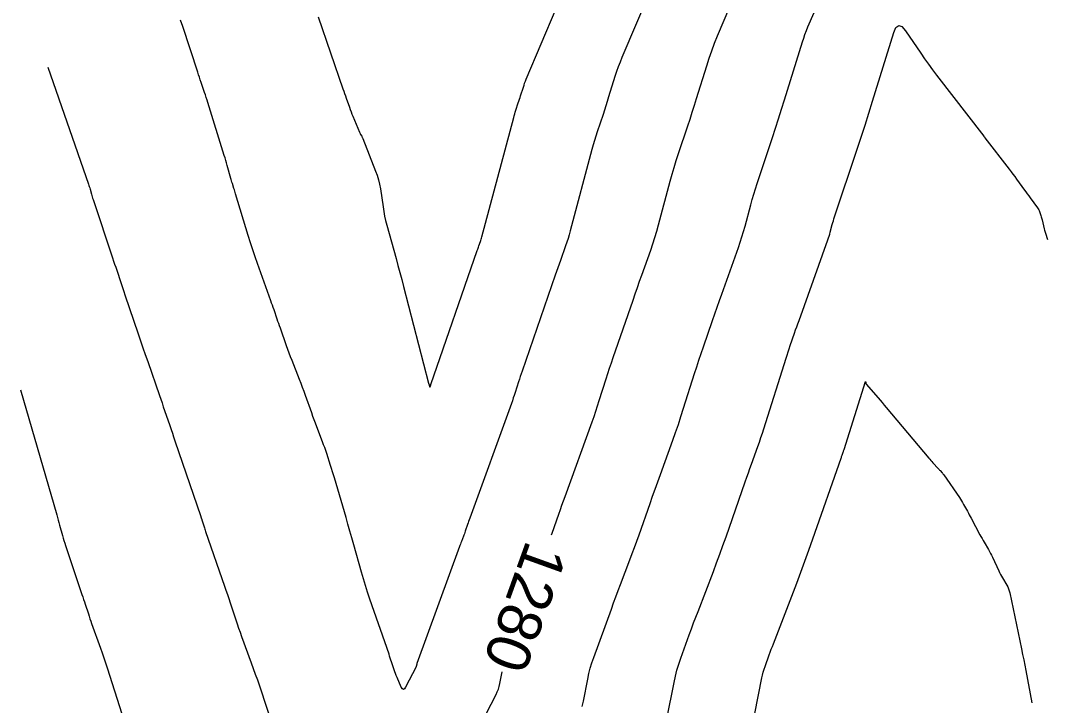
# Model space of a CAD drawing. Extents: x 658976 to 668726, y 639543 to 647196.
# Drawn here: x 661414.9 to 661555.9, y 640275.8 to 640369.9 of the extents above; entities that cross this region are included whole.
import ezdxf

# ---------------------------------------------------------------- set-up
doc = ezdxf.new("R2010")
doc.units = 0
for name, color, linetype in [('Ex_Contour Labels', 7, 'Continuous'), ('Ex_Major Contours', 7, 'Continuous'), ('Ex_Minor Contours', 7, 'Continuous')]:
    doc.layers.add(name, color=color, linetype=linetype)

msp = doc.modelspace()

# ---------------------------------------------------------------- linework, layer by layer
at = {"layer": 'Ex_Major Contours'}
for points in [[(661487.8, 640299.25), (661487.89, 640299.5), (661488.8, 640302.11), (661489.01, 640302.71), (661489.22, 640303.32), (661489.44, 640303.92), (661489.66, 640304.53), (661493.37, 640314.77), (661493.63, 640315.5), (661493.88, 640316.23), (661494.12, 640316.96), (661494.36, 640317.7), (661495.29, 640320.65), (661495.52, 640321.38), (661495.76, 640322.12), (661496.01, 640322.85), (661496.26, 640323.58), (661498.99, 640331.49), (661499.29, 640332.35), (661499.59, 640333.2), (661499.89, 640334.06), (661500.2, 640334.91), (661501.42, 640338.33), (661501.72, 640339.19), (661502, 640340.05), (661502.26, 640340.92), (661502.5, 640341.8), (661504.1, 640347.79), (661504.36, 640348.75), (661504.64, 640349.7), (661504.93, 640350.65), (661505.24, 640351.6), (661506.5, 640355.38), (661506.81, 640356.32), (661507.12, 640357.27), (661507.42, 640358.22), (661507.72, 640359.17), (661509.1, 640363.66), (661509.44, 640364.7), (661509.8, 640365.72), (661510.18, 640366.74), (661510.59, 640367.74), (661512.28, 640371.75)], [(661418.65, 640363.47), (661424.23, 640347.41), (661424.29, 640347.23), (661424.34, 640347.06), (661424.4, 640346.89), (661424.45, 640346.71), (661424.64, 640346.01), (661424.69, 640345.83), (661424.75, 640345.66), (661424.8, 640345.49), (661424.86, 640345.31), (661427.55, 640337.26), (661427.69, 640336.84), (661427.83, 640336.42), (661427.97, 640336), (661428.11, 640335.58), (661428.66, 640333.9), (661428.8, 640333.48), (661428.94, 640333.06), (661429.08, 640332.64), (661429.23, 640332.22), (661431.07, 640326.84), (661431.39, 640325.89), (661431.72, 640324.94), (661432.04, 640323.99), (661432.37, 640323.05), (661433.98, 640318.4), (661434.15, 640317.88), (661434.33, 640317.36), (661434.51, 640316.84), (661434.69, 640316.32), (661435.39, 640314.25), (661435.57, 640313.73), (661435.75, 640313.21), (661435.92, 640312.69), (661436.1, 640312.17), (661439.64, 640301.78), (661439.66, 640301.73), (661439.68, 640301.68), (661439.69, 640301.63), (661439.71, 640301.58), (661439.78, 640301.38), (661439.79, 640301.33), (661439.81, 640301.28), (661439.83, 640301.23), (661439.84, 640301.18), (661440.11, 640300.35), (661440.17, 640300.2), (661440.22, 640300.04), (661440.27, 640299.89), (661440.32, 640299.73), (661442.91, 640292.22), (661443.11, 640291.64), (661443.3, 640291.06), (661443.5, 640290.49), (661443.69, 640289.91), (661444.45, 640287.59), (661444.65, 640287.02), (661444.84, 640286.44), (661445.05, 640285.87), (661445.26, 640285.29), (661446.58, 640281.7), (661446.86, 640280.92), (661447.14, 640280.12), (661447.42, 640279.33), (661447.69, 640278.53), (661449.73, 640272.37)], [(661472.5, 640262.47), (661480.18, 640277.33), (661480.35, 640277.69), (661480.5, 640278.07), (661480.62, 640278.45), (661480.71, 640278.84), (661481.02, 640280.43), (661481.03, 640280.43)]]:
    msp.add_lwpolyline(points, dxfattribs=at)
at = {"layer": 'Ex_Minor Contours'}
for points in [[(661455.75, 640370.37), (661459.17, 640360.46), (661459.28, 640360.15), (661459.39, 640359.83), (661459.5, 640359.52), (661459.61, 640359.21), (661460.05, 640357.95), (661460.17, 640357.64), (661460.28, 640357.32), (661460.4, 640357.01), (661460.53, 640356.71), (661461.44, 640354.51), (661461.47, 640354.44), (661461.51, 640354.37), (661461.54, 640354.3), (661461.58, 640354.23), (661461.75, 640353.96), (661461.79, 640353.89), (661461.82, 640353.82), (661461.86, 640353.75), (661461.89, 640353.68), (661463.65, 640349.2), (661463.86, 640348.61), (661464.04, 640348), (661464.18, 640347.39), (661464.3, 640346.77), (661464.67, 640344.26), (661464.77, 640343.63), (661464.89, 640343.01), (661465.03, 640342.39), (661465.19, 640341.78), (661466.45, 640337.2), (661466.71, 640336.23), (661466.97, 640335.27), (661467.23, 640334.3), (661467.48, 640333.33), (661470.93, 640320.07), (661470.98, 640319.86), (661470.99, 640319.83), (661471, 640319.81), (661471, 640319.78), (661471.01, 640319.76), (661471.07, 640319.57), (661471.08, 640319.54), (661471.1, 640319.53), (661471.11, 640319.54), (661471.13, 640319.57), (661471.22, 640319.84), (661471.23, 640319.85), (661471.23, 640319.87), (661471.24, 640319.88), (661477.6, 640338.29), (661477.66, 640338.45), (661477.71, 640338.6), (661477.76, 640338.75), (661477.82, 640338.91), (661478.04, 640339.52), (661478.09, 640339.67), (661478.14, 640339.83), (661478.19, 640339.98), (661478.23, 640340.14), (661482.61, 640356.54), (661482.68, 640356.79), (661482.75, 640357.04), (661482.83, 640357.29), (661482.91, 640357.54), (661483.24, 640358.54), (661483.33, 640358.79), (661483.41, 640359.04), (661483.49, 640359.29), (661483.56, 640359.54), (661483.93, 640360.72), (661484.02, 640361), (661484.11, 640361.27), (661484.22, 640361.55), (661484.33, 640361.82), (661490.5, 640376.42)], [(661501.33, 640373.94), (661497.47, 640364.8), (661497.2, 640364.15), (661496.96, 640363.5), (661496.72, 640362.84), (661496.51, 640362.17), (661495.64, 640359.36), (661495.45, 640358.76), (661495.26, 640358.16), (661495.07, 640357.56), (661494.87, 640356.96), (661494.08, 640354.57), (661493.88, 640353.97), (661493.7, 640353.37), (661493.52, 640352.77), (661493.35, 640352.16), (661490.37, 640340.97), (661490.22, 640340.45), (661490.07, 640339.94), (661489.9, 640339.43), (661489.73, 640338.93), (661489.01, 640336.91), (661488.83, 640336.41), (661488.65, 640335.9), (661488.47, 640335.4), (661488.3, 640334.89), (661483.75, 640321.73), (661483.62, 640321.36), (661483.5, 640320.99), (661483.38, 640320.63), (661483.26, 640320.26), (661482.79, 640318.77), (661482.67, 640318.4), (661482.55, 640318.04), (661482.43, 640317.67), (661482.3, 640317.3), (661476.57, 640301.52), (661476.5, 640301.31), (661476.42, 640301.1), (661476.35, 640300.89), (661476.27, 640300.67), (661475.96, 640299.77), (661475.9, 640299.59), (661475.83, 640299.41), (661475.76, 640299.23), (661475.7, 640299.05), (661475.42, 640298.34), (661475.36, 640298.16), (661475.29, 640297.99), (661475.22, 640297.81), (661475.16, 640297.63), (661469.32, 640281.57), (661469.31, 640281.53), (661469.3, 640281.49), (661469.29, 640281.45), (661469.28, 640281.41), (661469.25, 640281.26), (661469.24, 640281.22), (661469.23, 640281.18), (661469.22, 640281.14), (661469.2, 640281.11), (661467.76, 640278.32), (661467.61, 640278.1), (661467.46, 640278.03), (661467.32, 640278.11), (661467.18, 640278.34), (661466.6, 640279.68), (661466.49, 640279.94), (661466.39, 640280.2), (661466.29, 640280.46), (661466.2, 640280.73), (661465.85, 640281.8), (661465.76, 640282.06), (661465.67, 640282.33), (661465.58, 640282.6), (661465.49, 640282.86), (661462.86, 640290.44), (661462.55, 640291.36), (661462.25, 640292.28), (661461.97, 640293.21), (661461.7, 640294.15), (661460.66, 640297.9), (661460.4, 640298.84), (661460.13, 640299.77), (661459.86, 640300.71), (661459.59, 640301.64), (661457.99, 640307.09), (661457.86, 640307.51), (661457.74, 640307.92), (661457.61, 640308.34), (661457.47, 640308.75), (661456.94, 640310.4), (661456.8, 640310.81), (661456.66, 640311.22), (661456.51, 640311.63), (661456.36, 640312.04), (661455.58, 640314.08), (661455.4, 640314.56), (661455.22, 640315.03), (661455.05, 640315.51), (661454.88, 640315.99), (661454.03, 640318.38), (661453.83, 640318.93), (661453.63, 640319.49), (661453.42, 640320.04), (661453.2, 640320.6), (661452.18, 640323.2), (661451.99, 640323.7), (661451.8, 640324.2), (661451.62, 640324.71), (661451.43, 640325.21), (661450.58, 640327.62), (661450.47, 640327.93), (661450.36, 640328.25), (661450.25, 640328.56), (661450.14, 640328.87), (661449.71, 640330.13), (661449.6, 640330.44), (661449.5, 640330.76), (661449.38, 640331.07), (661449.27, 640331.38), (661447.44, 640336.48), (661447.11, 640337.44), (661446.78, 640338.4), (661446.47, 640339.36), (661446.17, 640340.33), (661444.42, 640346.07), (661444.37, 640346.25), (661444.31, 640346.43), (661444.26, 640346.6), (661444.2, 640346.78), (661443.99, 640347.49), (661443.93, 640347.66), (661443.88, 640347.84), (661443.83, 640348.02), (661443.78, 640348.19), (661443.29, 640349.95), (661443.2, 640350.3), (661443.09, 640350.65), (661442.99, 640351), (661442.88, 640351.35), (661440.64, 640358.59), (661440.53, 640358.94), (661440.41, 640359.29), (661440.3, 640359.64), (661440.18, 640359.98), (661439.7, 640361.37), (661439.58, 640361.71), (661439.46, 640362.06), (661439.35, 640362.41), (661439.23, 640362.76), (661437.18, 640369.05), (661436.89, 640369.93)], [(661491.99, 640275.68), (661492.17, 640276.42), (661492.77, 640279.45), (661492.93, 640280.2), (661493.12, 640280.94), (661493.34, 640281.68), (661493.59, 640282.4), (661496.01, 640289.06), (661496.32, 640289.91), (661496.63, 640290.76), (661496.95, 640291.61), (661497.28, 640292.45), (661498.57, 640295.83), (661498.89, 640296.68), (661499.21, 640297.53), (661499.52, 640298.38), (661499.82, 640299.24), (661501.32, 640303.54), (661501.67, 640304.54), (661502.02, 640305.54), (661502.38, 640306.54), (661502.74, 640307.54), (661504.44, 640312.23), (661504.83, 640313.32), (661505.21, 640314.42), (661505.57, 640315.52), (661505.93, 640316.62), (661507.44, 640321.41), (661507.73, 640322.33), (661508.03, 640323.24), (661508.33, 640324.15), (661508.64, 640325.06), (661509.9, 640328.69), (661510.21, 640329.6), (661510.53, 640330.5), (661510.85, 640331.41), (661511.17, 640332.31), (661513.46, 640338.72), (661513.71, 640339.44), (661513.94, 640340.16), (661514.16, 640340.89), (661514.37, 640341.63), (661515.15, 640344.57), (661515.35, 640345.31), (661515.57, 640346.04), (661515.79, 640346.76), (661516.03, 640347.49), (661518.13, 640353.8), (661518.55, 640355.09), (661518.97, 640356.38), (661519.38, 640357.68), (661519.79, 640358.98), (661522.25, 640366.93), (661522.41, 640367.45), (661522.59, 640367.96), (661522.78, 640368.47), (661522.99, 640368.97), (661523.83, 640370.97)], [(661503.63, 640274.01), (661504.62, 640279), (661504.8, 640279.84), (661505.01, 640280.67), (661505.26, 640281.49), (661505.54, 640282.3), (661506.71, 640285.53), (661507.01, 640286.34), (661507.3, 640287.15), (661507.61, 640287.95), (661507.91, 640288.75), (661510.01, 640294.22), (661510.46, 640295.41), (661510.9, 640296.59), (661511.33, 640297.78), (661511.75, 640298.97), (661514.39, 640306.55), (661514.6, 640307.16), (661514.82, 640307.77), (661515.03, 640308.37), (661515.25, 640308.97), (661516.13, 640311.39), (661516.34, 640311.99), (661516.55, 640312.6), (661516.75, 640313.21), (661516.95, 640313.82), (661520, 640323.5), (661520.14, 640323.94), (661520.28, 640324.37), (661520.42, 640324.8), (661520.57, 640325.23), (661521.17, 640326.95), (661521.31, 640327.38), (661521.46, 640327.81), (661521.62, 640328.24), (661521.77, 640328.66), (661525.73, 640339.75), (661525.82, 640340.01), (661525.9, 640340.27), (661525.98, 640340.53), (661526.06, 640340.79), (661526.34, 640341.85), (661526.41, 640342.11), (661526.49, 640342.37), (661526.57, 640342.63), (661526.65, 640342.9), (661529.75, 640352.21), (661530.29, 640353.85), (661530.83, 640355.5), (661531.35, 640357.14), (661531.87, 640358.79), (661534.78, 640368.22), (661535.08, 640368.9), (661535.45, 640369.17), (661535.88, 640369.02), (661536.38, 640368.46), (661538.47, 640365.38), (661539, 640364.61), (661539.55, 640363.86), (661540.1, 640363.11), (661540.66, 640362.36), (661547.12, 640353.98), (661547.13, 640353.97), (661547.14, 640353.95), (661547.15, 640353.94), (661547.16, 640353.93), (661547.2, 640353.89), (661547.21, 640353.88), (661547.22, 640353.87), (661547.22, 640353.86), (661547.23, 640353.85), (661547.26, 640353.81), (661547.26, 640353.8), (661547.27, 640353.79), (661547.28, 640353.78), (661547.28, 640353.77), (661550.63, 640349.44), (661550.88, 640349.1), (661551.13, 640348.77), (661551.38, 640348.43), (661551.63, 640348.09), (661552.71, 640346.59), (661552.9, 640346.32), (661553.1, 640346.05), (661553.3, 640345.78), (661553.5, 640345.51), (661554.52, 640344.14), (661554.6, 640344.02), (661554.67, 640343.89), (661554.73, 640343.76), (661554.79, 640343.62), (661554.97, 640343.07), (661555.02, 640342.93), (661555.06, 640342.79), (661555.1, 640342.65), (661555.13, 640342.5), (661555.44, 640341.24), (661555.48, 640341.09), (661555.52, 640340.95), (661555.56, 640340.81), (661555.6, 640340.66), (661555.87, 640339.81)], [(661514.74, 640269.83), (661516.67, 640279.61), (661516.76, 640280.01), (661516.87, 640280.41), (661516.98, 640280.81), (661517.12, 640281.2), (661517.68, 640282.76), (661517.83, 640283.15), (661517.97, 640283.54), (661518.12, 640283.92), (661518.26, 640284.31), (661521.45, 640292.62), (661522.02, 640294.13), (661522.59, 640295.65), (661523.14, 640297.17), (661523.68, 640298.7), (661527.54, 640309.79), (661527.58, 640309.89), (661527.61, 640309.99), (661527.65, 640310.09), (661527.68, 640310.19), (661527.83, 640310.59), (661527.86, 640310.69), (661527.9, 640310.79), (661527.93, 640310.89), (661527.96, 640310.99), (661530.89, 640320.28), (661530.89, 640320.29), (661530.9, 640320.29), (661530.9, 640320.29), (661530.91, 640320.28), (661530.92, 640320.22), (661530.93, 640320.2), (661530.93, 640320.19), (661530.93, 640320.17), (661530.94, 640320.16), (661530.96, 640320.02), (661530.97, 640319.99), (661530.98, 640319.97), (661530.99, 640319.94), (661531.01, 640319.92), (661532.64, 640318.04), (661532.92, 640317.72), (661533.2, 640317.4), (661533.48, 640317.07), (661533.75, 640316.75), (661539.61, 640309.78), (661539.74, 640309.62), (661539.88, 640309.47), (661540.02, 640309.31), (661540.16, 640309.15), (661540.87, 640308.37), (661540.94, 640308.3), (661541.01, 640308.22), (661541.07, 640308.15), (661541.14, 640308.07), (661541.4, 640307.78), (661541.47, 640307.71), (661541.53, 640307.63), (661541.59, 640307.55), (661541.65, 640307.47), (661543.79, 640304.37), (661543.94, 640304.14), (661544.09, 640303.91), (661544.23, 640303.68), (661544.36, 640303.44), (661544.89, 640302.49), (661545.02, 640302.25), (661545.15, 640302.01), (661545.28, 640301.77), (661545.41, 640301.53), (661546.61, 640299.27), (661546.75, 640299.01), (661546.89, 640298.75), (661547.04, 640298.49), (661547.19, 640298.24), (661547.78, 640297.22), (661547.93, 640296.96), (661548.07, 640296.7), (661548.21, 640296.44), (661548.33, 640296.17), (661549.19, 640294.32), (661549.31, 640294.07), (661549.44, 640293.82), (661549.57, 640293.57), (661549.71, 640293.33), (661550.28, 640292.35), (661550.42, 640292.1), (661550.53, 640291.85), (661550.62, 640291.58), (661550.69, 640291.31), (661552.31, 640283.58), (661552.46, 640282.84), (661552.61, 640282.1), (661552.75, 640281.36), (661552.89, 640280.62), (661553.73, 640276.18)], [(661414.91, 640319.17), (661419.89, 640301.98), (661419.99, 640301.63), (661420.09, 640301.28), (661420.18, 640300.93), (661420.28, 640300.57), (661420.67, 640299.16), (661420.76, 640298.81), (661420.87, 640298.46), (661420.98, 640298.11), (661421.09, 640297.77), (661423.34, 640291.05), (661423.45, 640290.72), (661423.56, 640290.39), (661423.67, 640290.06), (661423.78, 640289.73), (661424.22, 640288.4), (661424.33, 640288.07), (661424.44, 640287.74), (661424.55, 640287.41), (661424.67, 640287.08), (661425.87, 640283.71), (661426.1, 640283.04), (661426.33, 640282.36), (661426.56, 640281.69), (661426.78, 640281.01), (661428.81, 640274.66)]]:
    msp.add_lwpolyline(points, dxfattribs=at)

# ---------------------------------------------------------------- texts
at = {"layer": 'Ex_Contour Labels'}
msp.add_text('1280', height=6, rotation=250.2014, dxfattribs=at).set_placement((661484.41, 640298.7))

doc.saveas('drawing.dxf')
